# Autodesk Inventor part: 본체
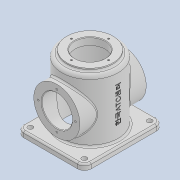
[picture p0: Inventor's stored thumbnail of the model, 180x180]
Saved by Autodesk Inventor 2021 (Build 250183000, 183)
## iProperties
Created: 2021-02
Part Number: 본체
Material: 알루미늄 6061
Document SubType Name: Modeling
Designer: sjtjd
Density: 2.7 g/cm^3
Appearance: 기본값
Author: sjtjd
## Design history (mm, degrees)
sketch "스케치1"
  geometry: L1 (70, -60)-(-70, -60); L2 (-70, -60)-(-70, 60); L3 (-70, 60)-(70, 60); L4 (70, 60)-(70, -60); L5 (70, -60)-(-70, 60); L6 (-70, -60)-(70, 60); 1 further point
  constraints: 12 end point, 2 midpoint, 2 parallel, 1 horizontal, 1 perpendicular
  dimensions: "d0" = 140 distance of L2.end L3.end; "d1" = 120 distance of L1.end L2.end
extrude "돌출1" new body sketch "스케치1" distance "d2" = 10; taper "d3" = 0 deg
sketch "스케치2"
  geometry: C1 r 50 at (0, 0); 1 further point
  constraints: 1 centre point, 1 coincident
  dimensions: "d4" = 100 diameter of C1
extrude "돌출2" join sketch "스케치2" distance "d5" = 110; taper "d6" = 0 deg
sketch "스케치3"
  geometry: C1 r 42 at (0, 0); 1 further point
  constraints: 1 centre point, 1 coincident
  dimensions: "d7" = 84 diameter of C1
extrude "돌출3" cut sketch "스케치3" distance "d8" = 112; taper "d9" = 0 deg
sketch "스케치4"
  geometry: C1 r 27 at (0, 0); 1 further point
  constraints: 1 centre point, 1 coincident
  dimensions: "d10" = 54 diameter of C1
extrude "돌출4" cut sketch "스케치4" extent not by distance; stored distance "d11" = 0; taper "d12" = 0 deg
node "작업 평면1"
sketch "스케치5"
  geometry: L1 (0, 60)-(0, -60) reference; C1 r 41 at (59.98, 0); 2 further points
  constraints: 1 centre point, 1 horizontal alignment, 1 midpoint
  dimensions: "d14" = 82 diameter of C1; "d15" = 59.98 distance from line of L1 C1.centre
extrude "돌출5" join sketch "스케치5" stored distance "d16" = 118; taper "d17" = 0 deg
sketch "스케치6"
  geometry: C1 r 41 at (0, 0) reference; C2 r 27 at (0, 0); 1 further point
  constraints: 1 centre point, 1 coincident
  dimensions: "d18" = 54 diameter of C2
extrude "돌출6" cut sketch "스케치6" extent not by distance; stored distance "d19" = 0; taper "d20" = 0 deg
sketch "스케치7"
  geometry: C1 r 41 at (0, 0) reference; A1 r 33 centre (0, 0) between (0, 33) and (33, 0); 3 further points
  constraints: 4 point on circle, 1 centre point, 1 coincident, 1 horizontal alignment, 1 vertical alignment
  dimensions: "d21" = 66 diameter of A1; "d22" = 66 distance of point (0, -33) A1.start; "d23" = 66 distance of point (-33, 0) A1.end
hole "구멍1" sketch "스케치7" at (0, 33), (33, 0), (0, -33), (-33, 0) diameter "d24" = 3.242; stored, may be unused: countersink angle "d28" = 82 deg, drill point angle "d30" = 118 deg; dims "d25" = 8, "d26" = 3.023, "d27" = 2, "d29" = 10
sketch "스케치8"
  geometry: C1 r 41 at (0, 0); C2 r 27 at (0, 0) reference; 1 further point
  constraints: 1 centre point, 1 coincident
  dimensions: "d31" = 82 diameter of C1
extrude "돌출7" join sketch "스케치8" distance "d32" = 5; taper "d33" = 0 deg
fillet "모깎기1" dims "d34" = 12
sketch "스케치9"
  geometry: A1 r 12 centre (-58, 48) between (-58, 60) and (-70, 48) reference; A2 r 12 centre (-58, -48) between (-70, -48) and (-58, -60) reference; A3 r 12 centre (58, -48) between (58, -60) and (70, -48) reference; A4 r 12 centre (58, 48) between (70, 48) and (58, 60) reference; 5 further points
  constraints: 4 coincident
hole "구멍2" sketch "스케치9" at (-58, 48), (58, 48), (58, -48), (-58, -48) diameter "d35" = 9; stored, may be unused: countersink angle "d39" = 82 deg, drill point angle "d41" = 118 deg; dims "d36" = 8, "d37" = 3.023, "d38" = 2, "d40" = 10
sketch "스케치10" dims "d42" = 66
  geometry: 3 further points
  constraints: 2 vertical alignment, 1 coincident, 2 other
hole "구멍3" sketch "스케치10" diameter "d43" = 3.242; stored, may be unused: countersink angle "d47" = 82 deg, drill point angle "d49" = 118 deg; dims "d44" = 8, "d45" = 3.023, "d46" = 2, "d48" = 10
fillet "모깎기2" dims "d53" = 6
fillet "모깎기3" dims "d54" = 3
fillet "모깎기4" dims "d55" = 3
fillet "모깎기5" dims "d56" = 3
fillet "모깎기6" dims "d57" = 3
chamfer "모따기1" distance "d58" = 1; stored, may be unused: second distance "d59" = 2, angle "d60" = 45 deg
node "작업 평면2"
sketch "스케치11"
  geometry: L1 (-58, 0)-(58, 0) reference; 2 further points
  constraints: 1 vertical alignment, 1 other
  dimensions: "d62" = 66 distance from line of L1 point (0, 66)
feature "엠보싱1" sketch "스케치11" dims "d0" = 140, "d1" = 120, "d63" = 0.5, "d64" = 0
node "솔리드1"
mirror "미러1"
mirror "미러2"
pattern_circular "원형 패턴1" dims angle "d51" = 360 deg
feature "A9D066F2-1C7D-4E18-AEED-F7BC21143FA4" dims "d35" = 9, "d36" = 8, "d37" = 3.023, "d38" = 2, "d39" = 82 deg, "d40" = 10, "d41" = 118 deg
other parameters: "d13" = 59, "d61" = -69
